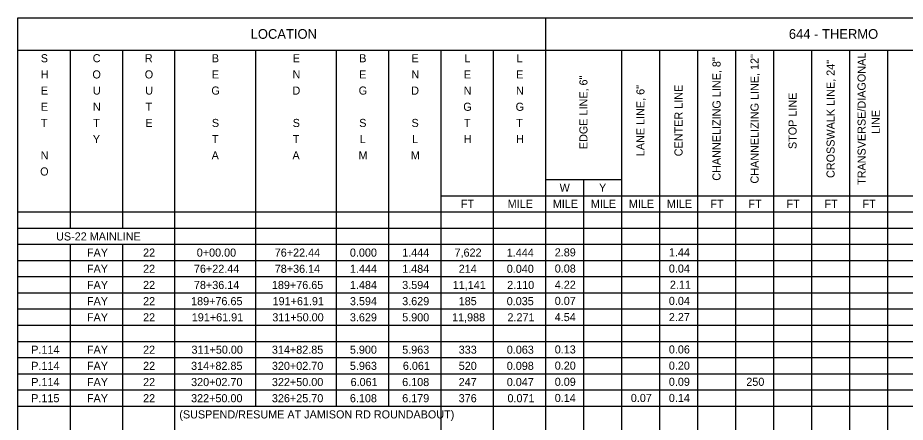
# Model space of a CAD drawing. Extents: x 12522 to 13018, y 1124 to 1902.
# Drawn here: x 12873.15 to 12888.52, y 1818.65 to 1825.65 of the extents above; entities that cross this region are included whole.
import ezdxf

# ---------------------------------------------------------------- set-up
doc = ezdxf.new("R2010")
doc.units = 0
for name, color, linetype in [('SC_Scratch1', 7, 'Continuous'), ('SH_Data', 7, 'Continuous'), ('SH_Text', 7, 'Continuous')]:
    doc.layers.add(name, color=color, linetype=linetype)

msp = doc.modelspace()

# ---------------------------------------------------------------- linework, layer by layer
at = {"layer": 'SC_Scratch1'}
msp.add_lwpolyline([(12873.148, 1825.65), (12903.648, 1825.65), (12903.648, 1804.65), (12873.148, 1804.65)], close=True, dxfattribs=at)
at = {"layer": 'SH_Data'}
for p, q in [((12882.289, 1825.65), (12882.289, 1804.667)), ((12873.148, 1825.09), (12903.668, 1825.09)), ((12874.054, 1825.09), (12874.054, 1822.01)), ((12874.96, 1825.09), (12874.96, 1822.01)), ((12875.865, 1825.09), (12875.865, 1805.21)), ((12877.265, 1825.09), (12877.265, 1818.93)), ((12878.665, 1825.09), (12878.665, 1818.93)), ((12879.571, 1825.09), (12879.571, 1818.93)), ((12880.477, 1825.09), (12880.477, 1805.21)), ((12881.383, 1825.09), (12881.383, 1805.21)), ((12883.607, 1825.09), (12883.607, 1804.667)), ((12884.265, 1825.09), (12884.265, 1804.667)), ((12884.924, 1825.09), (12884.924, 1804.667)), ((12885.583, 1825.09), (12885.583, 1804.667)), ((12886.242, 1825.09), (12886.242, 1804.667)), ((12886.901, 1825.09), (12886.901, 1804.667)), ((12887.56, 1825.09), (12887.56, 1804.667)), ((12888.218, 1825.09), (12888.218, 1804.667)), ((12882.289, 1822.85), (12883.607, 1822.85)), ((12882.948, 1822.85), (12882.948, 1805.21)), ((12880.477, 1822.57), (12903.668, 1822.57)), ((12873.148, 1822.29), (12903.668, 1822.29)), ((12873.148, 1822.01), (12903.668, 1822.01)), ((12873.148, 1821.73), (12903.668, 1821.73)), ((12874.054, 1821.73), (12874.054, 1805.21)), ((12874.96, 1821.73), (12874.96, 1805.21)), ((12873.148, 1821.45), (12903.668, 1821.45)), ((12873.148, 1821.17), (12903.668, 1821.17)), ((12873.148, 1820.89), (12903.668, 1820.89)), ((12873.148, 1820.61), (12903.668, 1820.61)), ((12873.148, 1820.33), (12903.668, 1820.33)), ((12873.148, 1820.05), (12903.668, 1820.05)), ((12873.148, 1819.77), (12903.668, 1819.77)), ((12873.148, 1819.49), (12903.668, 1819.49)), ((12873.148, 1819.21), (12903.668, 1819.21)), ((12873.148, 1818.93), (12903.668, 1818.93))]:
    msp.add_line(p, q, dxfattribs=at)

# ---------------------------------------------------------------- texts
at = {"layer": 'SH_Text'}
for s, height, p in [('LOCATION', 0.168, (12877.183, 1825.286)), ('644 - THERMO', 0.168, (12886.507, 1825.286)), ('S', 0.14, (12873.547, 1824.88)), ('C', 0.14, (12874.447, 1824.88)), ('R', 0.14, (12875.35, 1824.88)), ('B', 0.14, (12876.511, 1824.88)), ('E', 0.14, (12877.911, 1824.88)), ('B', 0.14, (12879.064, 1824.88)), ('E', 0.14, (12879.97, 1824.88)), ('L', 0.14, (12880.884, 1824.88)), ('L', 0.14, (12881.79, 1824.88)), ('H', 0.14, (12873.544, 1824.6)), ('O', 0.14, (12874.442, 1824.6)), ('O', 0.14, (12875.348, 1824.6)), ('E', 0.14, (12876.511, 1824.6)), ('N', 0.14, (12877.909, 1824.6)), ('E', 0.14, (12879.064, 1824.6)), ('N', 0.14, (12879.968, 1824.6)), ('E', 0.14, (12880.876, 1824.6)), ('E', 0.14, (12881.782, 1824.6)), ('E', 0.14, (12873.547, 1824.32)), ('U', 0.14, (12874.45, 1824.32)), ('U', 0.14, (12875.356, 1824.32)), ('G', 0.14, (12876.503, 1824.32)), ('D', 0.14, (12877.907, 1824.32)), ('G', 0.14, (12879.055, 1824.32)), ('D', 0.14, (12879.965, 1824.32)), ('N', 0.14, (12880.874, 1824.32)), ('N', 0.14, (12881.78, 1824.32)), ('E', 0.14, (12873.547, 1824.04)), ('N', 0.14, (12874.45, 1824.04)), ('T', 0.14, (12875.361, 1824.04)), ('G', 0.14, (12880.867, 1824.04)), ('G', 0.14, (12881.773, 1824.04)), ('T', 0.14, (12873.549, 1823.76)), ('T', 0.14, (12874.455, 1823.76)), ('E', 0.14, (12875.359, 1823.76)), ('S', 0.14, (12876.511, 1823.76)), ('S', 0.14, (12877.911, 1823.76)), ('S', 0.14, (12879.064, 1823.76)), ('S', 0.14, (12879.97, 1823.76)), ('T', 0.14, (12880.878, 1823.76)), ('T', 0.14, (12881.784, 1823.76)), ('Y', 0.14, (12874.449, 1823.48)), ('T', 0.14, (12876.513, 1823.48)), ('T', 0.14, (12877.913, 1823.48)), ('L', 0.14, (12879.073, 1823.48)), ('L', 0.14, (12879.978, 1823.48)), ('H', 0.14, (12880.874, 1823.48)), ('H', 0.14, (12881.78, 1823.48)), ('N', 0.14, (12873.544, 1823.2)), ('A', 0.14, (12876.507, 1823.2)), ('A', 0.14, (12877.907, 1823.2)), ('M', 0.14, (12879.052, 1823.2)), ('M', 0.14, (12879.958, 1823.2)), ('O', 0.14, (12873.536, 1822.92)), ('W', 0.14, (12882.536, 1822.64)), ('Y', 0.14, (12883.219, 1822.64)), ('FT', 0.14, (12880.824, 1822.36)), ('MILE', 0.14, (12881.635, 1822.36)), ('MILE', 0.14, (12882.418, 1822.36)), ('MILE', 0.14, (12883.077, 1822.36)), ('MILE', 0.14, (12883.735, 1822.36)), ('MILE', 0.14, (12884.394, 1822.36)), ('FT', 0.14, (12885.148, 1822.36)), ('FT', 0.14, (12885.807, 1822.36)), ('FT', 0.14, (12886.466, 1822.36)), ('FT', 0.14, (12887.124, 1822.36)), ('FT', 0.14, (12887.783, 1822.36)), ('US-22 MAINLINE', 0.14, (12873.812, 1821.796)), ('FAY', 0.14, (12874.347, 1821.516)), ('22', 0.14, (12875.319, 1821.516)), ('0+00.00', 0.14, (12876.249, 1821.516)), ('76+22.44', 0.14, (12877.6, 1821.516)), ('0.000', 0.14, (12878.902, 1821.516)), ('1.444', 0.14, (12879.808, 1821.516)), ('7,622', 0.14, (12880.715, 1821.516)), ('1.444', 0.14, (12881.62, 1821.516)), ('2.89', 0.14, (12882.451, 1821.52)), ('1.44', 0.14, (12884.428, 1821.52)), ('FAY', 0.14, (12874.347, 1821.236)), ('22', 0.14, (12875.319, 1821.236)), ('76+22.44', 0.14, (12876.2, 1821.236)), ('78+36.14', 0.14, (12877.6, 1821.236)), ('1.444', 0.14, (12878.903, 1821.236)), ('1.484', 0.14, (12879.808, 1821.236)), ('214', 0.14, (12880.788, 1821.236)), ('0.040', 0.14, (12881.62, 1821.236)), ('0.08', 0.14, (12882.451, 1821.24)), ('0.04', 0.14, (12884.428, 1821.24)), ('FAY', 0.14, (12874.347, 1820.956)), ('22', 0.14, (12875.319, 1820.956)), ('78+36.14', 0.14, (12876.2, 1820.956)), ('189+76.65', 0.14, (12877.551, 1820.956)), ('1.484', 0.14, (12878.903, 1820.956)), ('3.594', 0.14, (12879.808, 1820.956)), ('11,141', 0.14, (12880.684, 1820.956)), ('2.110', 0.14, (12881.627, 1820.956)), ('4.22', 0.14, (12882.452, 1820.96)), ('2.11', 0.14, (12884.446, 1820.96)), ('FAY', 0.14, (12874.347, 1820.676)), ('22', 0.14, (12875.319, 1820.676)), ('189+76.65', 0.14, (12876.151, 1820.676)), ('191+61.91', 0.14, (12877.563, 1820.676)), ('3.594', 0.14, (12878.903, 1820.676)), ('3.629', 0.14, (12879.808, 1820.676)), ('185', 0.14, (12880.787, 1820.676)), ('0.035', 0.14, (12881.619, 1820.676)), ('0.07', 0.14, (12882.451, 1820.68)), ('0.04', 0.14, (12884.428, 1820.68)), ('FAY', 0.14, (12874.347, 1820.396)), ('22', 0.14, (12875.319, 1820.396)), ('191+61.91', 0.14, (12876.163, 1820.396)), ('311+50.00', 0.14, (12877.558, 1820.396)), ('3.629', 0.14, (12878.902, 1820.396)), ('5.900', 0.14, (12879.808, 1820.396)), ('11,988', 0.14, (12880.672, 1820.396)), ('2.271', 0.14, (12881.632, 1820.396)), ('4.54', 0.14, (12882.451, 1820.4)), ('2.27', 0.14, (12884.428, 1820.4)), ('P.114', 0.14, (12873.382, 1819.836)), ('FAY', 0.14, (12874.347, 1819.836)), ('22', 0.14, (12875.319, 1819.836)), ('311+50.00', 0.14, (12876.158, 1819.836)), ('314+82.85', 0.14, (12877.551, 1819.836)), ('5.900', 0.14, (12878.902, 1819.836)), ('5.963', 0.14, (12879.808, 1819.836)), ('333', 0.14, (12880.787, 1819.836)), ('0.063', 0.14, (12881.62, 1819.836)), ('0.13', 0.14, (12882.451, 1819.84)), ('0.06', 0.14, (12884.428, 1819.84)), ('P.114', 0.14, (12873.382, 1819.556)), ('FAY', 0.14, (12874.347, 1819.556)), ('22', 0.14, (12875.319, 1819.556)), ('314+82.85', 0.14, (12876.151, 1819.556)), ('320+02.70', 0.14, (12877.551, 1819.556)), ('5.963', 0.14, (12878.902, 1819.556)), ('6.061', 0.14, (12879.82, 1819.556)), ('520', 0.14, (12880.788, 1819.556)), ('0.098', 0.14, (12881.62, 1819.556)), ('0.20', 0.14, (12882.451, 1819.56)), ('0.20', 0.14, (12884.428, 1819.56)), ('0.09', 0.14, (12882.451, 1819.28)), ('0.09', 0.14, (12884.428, 1819.28)), ('250', 0.14, (12885.77, 1819.28)), ('P.114', 0.14, (12873.382, 1819.276)), ('FAY', 0.14, (12874.347, 1819.276)), ('22', 0.14, (12875.319, 1819.276)), ('320+02.70', 0.14, (12876.151, 1819.276)), ('322+50.00', 0.14, (12877.551, 1819.276)), ('6.061', 0.14, (12878.914, 1819.276)), ('6.108', 0.14, (12879.808, 1819.276)), ('247', 0.14, (12880.787, 1819.276)), ('0.047', 0.14, (12881.62, 1819.276)), ('P.115', 0.14, (12873.381, 1818.996)), ('FAY', 0.14, (12874.347, 1818.996)), ('22', 0.14, (12875.319, 1818.996)), ('322+50.00', 0.14, (12876.151, 1818.996)), ('326+25.70', 0.14, (12877.551, 1818.996)), ('6.108', 0.14, (12878.902, 1818.996)), ('6.179', 0.14, (12879.808, 1818.996)), ('376', 0.14, (12880.787, 1818.996)), ('0.071', 0.14, (12881.632, 1818.996)), ('0.14', 0.14, (12882.451, 1819)), ('0.07', 0.14, (12883.769, 1819)), ('0.14', 0.14, (12884.428, 1819)), ('(SUSPEND/RESUME AT JAMISON RD ROUNDABOUT)', 0.14, (12875.947, 1818.716))]:
    msp.add_text(s, height=height, dxfattribs=at).set_placement(p)
for s, p in [('CHANNELIZING LINE, 8"', (12885.324, 1822.83)), ('CHANNELIZING LINE, 12"', (12885.983, 1822.781)), ('TRANSVERSE/DIAGONAL ', (12887.837, 1822.757)), ('CROSSWALK LINE, 24"', (12887.3, 1822.877)), ('EDGE LINE, 6"', (12883.018, 1823.376)), ('LANE LINE, 6"', (12884.006, 1823.255)), ('CENTER LINE', (12884.665, 1823.253)), ('STOP LINE', (12886.641, 1823.378)), ('LINE', (12888.082, 1823.639))]:
    msp.add_text(s, height=0.14, rotation=90, dxfattribs=at).set_placement(p)

doc.saveas('drawing.dxf')
